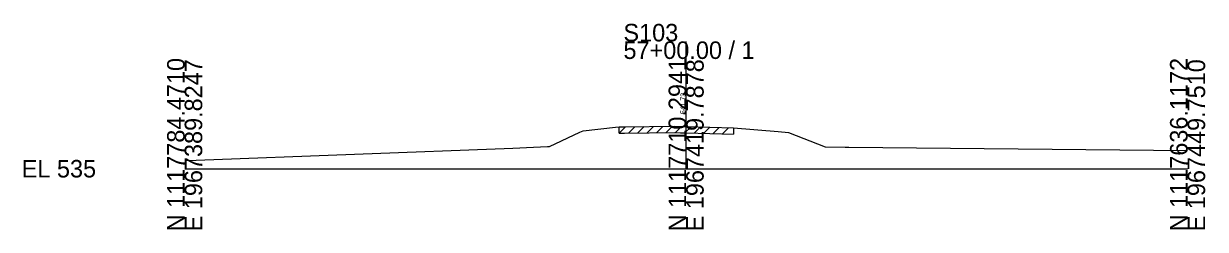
# Model space of a CAD drawing. Extents: x -26 to 163, y -10 to 45020.
# Drawn here: x -25.7 to 162.8, y 16990.3 to 17023.2 of the extents above; entities that cross this region are included whole.
import ezdxf

# ---------------------------------------------------------------- set-up
doc = ezdxf.new("R2010")
doc.units = 0
for name, color, linetype in [('RD_GPK_XS_Cell', 7, 'Continuous'), ('RD_XS_ExGround', 7, 'Continuous'), ('RD_XS_ExPaveRet', 7, 'Continuous'), ('RD_XS_TX_Elev_EX', 7, 'Continuous')]:
    doc.layers.add(name, color=color, linetype=linetype)

msp = doc.modelspace()

# ---------------------------------------------------------------- linework, layer by layer
at = {"layer": 'RD_GPK_XS_Cell'}
for p, q in [((80, 17000), (80, 17020.33)), ((0, 17000), (80, 17000)), ((80, 17000), (160, 17000))]:
    msp.add_line(p, q, dxfattribs=at)
at = {"layer": 'RD_XS_ExGround'}
for p, q in [((58.21, 17003.57), (63.03, 17005.83)), ((63.03, 17005.83), (63.57, 17006.07)), ((63.57, 17006.07), (68.72, 17006.62)), ((68.72, 17006.62), (69.3, 17006.69)), ((69.3, 17006.69), (70.15, 17006.69)), ((70.15, 17006.69), (78.11, 17006.78)), ((78.11, 17006.78), (79.11, 17006.75)), ((79.11, 17006.75), (80, 17006.73)), ((80, 17006.73), (87.54, 17006.52)), ((87.54, 17006.52), (94.69, 17005.92)), ((94.69, 17005.92), (96.33, 17005.78)), ((96.33, 17005.78), (102.19, 17003.51)), ((1.81, 17001.37), (52.37, 17003.3)), ((52.37, 17003.3), (55.64, 17003.44)), ((55.64, 17003.44), (57.86, 17003.56)), ((57.86, 17003.56), (58.21, 17003.57)), ((102.19, 17003.51), (105.35, 17003.43)), ((105.35, 17003.43), (105.94, 17003.45)), ((105.94, 17003.45), (160, 17002.91)), ((0, 17001.33), (1.81, 17001.37))]:
    msp.add_line(p, q, dxfattribs=at)
at = {"layer": 'RD_XS_ExPaveRet'}
for p, q in [((69.3, 17005.69), (70.31, 17006.7)), ((69.3, 17005.69), (69.3, 17006.69)), ((69.3, 17005.69), (70.15, 17005.69)), ((70.15, 17005.69), (78.11, 17005.78)), ((70.8, 17005.7), (71.81, 17006.71)), ((72.3, 17005.72), (73.31, 17006.73)), ((73.8, 17005.73), (74.81, 17006.74)), ((75.3, 17005.75), (76.31, 17006.76)), ((76.8, 17005.76), (77.81, 17006.77)), ((78.11, 17005.78), (79.11, 17005.75)), ((78.3, 17005.77), (79.28, 17006.75)), ((79.11, 17005.75), (80, 17005.73)), ((79.8, 17005.73), (80.78, 17006.71)), ((80, 17005.73), (87.54, 17005.52)), ((81.3, 17005.69), (82.28, 17006.67)), ((82.8, 17005.65), (83.78, 17006.62)), ((84.3, 17005.61), (85.28, 17006.58)), ((85.8, 17005.57), (86.78, 17006.54)), ((87.54, 17006.52), (87.54, 17005.52))]:
    msp.add_line(p, q, dxfattribs=at)

# ---------------------------------------------------------------- texts
at = {"layer": 'RD_GPK_XS_Cell'}
for s, p in [('S103', (70, 17020.33)), ('57+00.00 / 1', (70, 17017.53)), ('EL 535', (-26, 16998.6))]:
    msp.add_text(s, height=2.8, dxfattribs=at).set_placement(p)
for s, p in [('N 1117784.4710', (0, 16990)), ('E 1967389.8247', (2.8, 16990)), ('N 1117710.2941', (80, 16990)), ('E 1967419.7878', (82.8, 16990)), ('N 1117636.1172', (160, 16990)), ('E 1967449.7510', (162.8, 16990))]:
    msp.add_text(s, height=2.8, rotation=90, dxfattribs=at).set_placement(p)
at = {"layer": 'RD_XS_TX_Elev_EX'}
msp.add_text('541.73', height=0.8, rotation=90, dxfattribs=at).set_placement((79.9, 17008.73))

doc.saveas('drawing.dxf')
